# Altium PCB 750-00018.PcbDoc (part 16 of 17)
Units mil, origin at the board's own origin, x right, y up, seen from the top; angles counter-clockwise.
Board outline 7086.64 x 6299.21 mil, 8 copper layers (Top Layer, L2, L3, L4, L5, L6, L7, Bottom Layer), stack 60.6 mil thick; 1356 components, 1054 nets, 4851 pads, 4296 vias.
Unrouted connection lines stored in the file: 12.
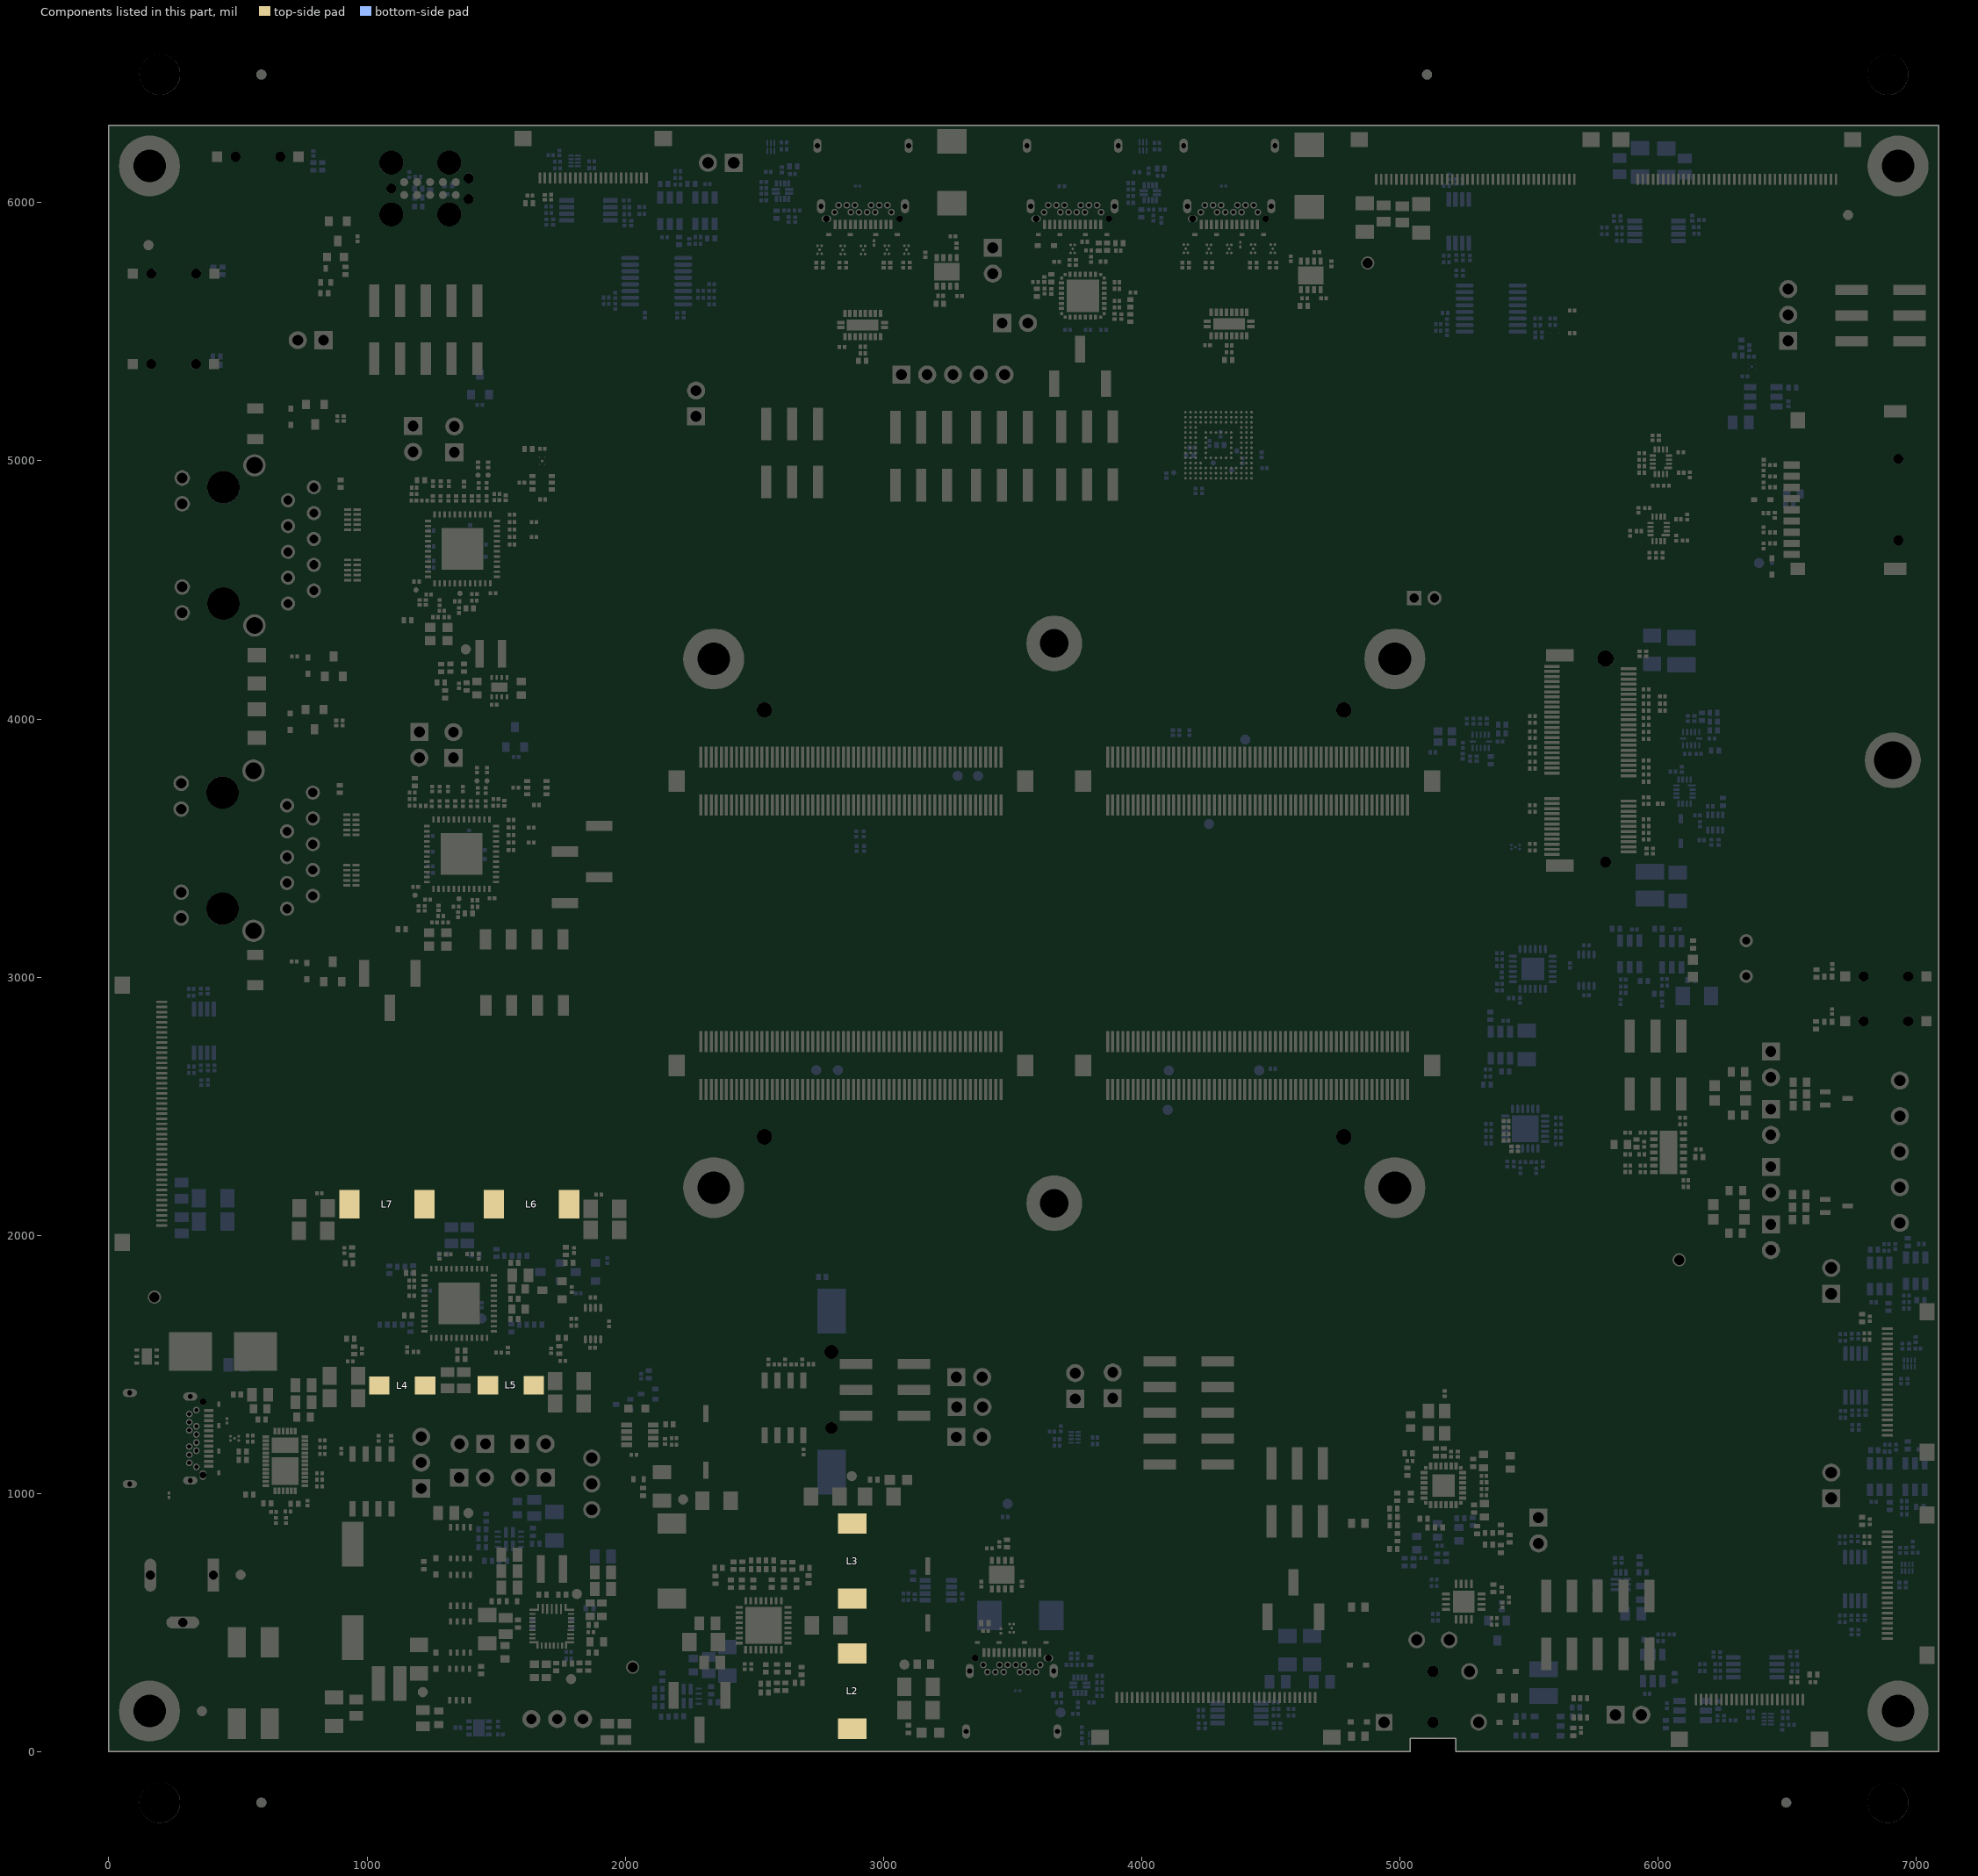
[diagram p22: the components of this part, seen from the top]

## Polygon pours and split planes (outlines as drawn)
GND on Top Layer "TOP-GND" (solid, remove dead copper, pour order 107): 0,0 5038.89,0 5038.89,51.18 5216.05,51.18 5216.05,0 7086.63,0 7086.63,6299.21 0,6299.21
AGND on Top Layer "TOP-AGND" (solid, remove dead copper, pour order 101): 4838.02,0 5038.89,0 5038.89,51.18 5216.05,51.18 5216.05,0 5417.44,0 5417.44,322.73 5507.23,412.52 5507.23,670.38 5615.15,778.3 5615.15,1028.18 5522.74,1120.59 5219.87,1120.59 5219.87,981.24 5116.08,981.24 5116.08,1182.17 5140.89,1206.98 5140.89,1279.36 5019.59,1279.36 4838.02,1097.79
VDD_5V on Top Layer "TOP-VDD_5V" (solid, remove dead copper, pour order 74): 2491.73,6081.68 2491.73,6033.64 2498.49,6026.89 2617.75,6026.89 2633.56,6011.07 2633.56,5843.45 2646.31,5830.7 2671.37,5830.7 2686.05,5845.37 2686.05,6162.48 2661.87,6186.66 2637.68,6186.66 2631.69,6180.67 2631.69,6101.64 2619.32,6089.26 2499.31,6089.26
VDD_5V on Top Layer "TOP-VDD_5V" (solid, remove dead copper, pour order 75): 3913.91,5977.95 4070.31,5821.56 4090.86,5821.56 4098.16,5828.85 4098.16,6168.01 4088.53,6177.64 4067.97,6177.64 4057.86,6167.54 4057.87,6039.46 4033.87,6015.46 3990.35,6015.46 3973.99,6031.82 3973.99,6078.98 3960.63,6092.34 3926.25,6092.34 3913.91,6080.01
GND_CHASE on Top Layer "TOP-GND_CHASE" (solid, remove dead copper, pour order 100): 7.28,5134.02 7.28,3028.3 650.91,3028.3 650.91,3982.23 518.38,3982.23 487.14,4013.47 487.14,4157.43 522.37,4192.66 654.86,4192.66 654.86,5134.02
CSI_HV on L3 "TOP-GND" (solid, remove dead copper, pour order 16): 4350.39,567.99 4350.39,461.36 4711.61,461.36 4711.61,1110.12 4930.51,1329.02 5319.83,1329.02 5445.32,1203.53 5542.87,1203.53 5666.82,1079.58 5666.82,668.48 5824.8,668.48 5824.8,1137.43 5475.78,1486.45 4742.98,1486.45 4464.85,1208.32 4464.85,682.45
GND on L3 "L3-GND" (solid, remove dead copper, pour order 121): 0,0 5038.89,0 5038.89,51.18 5216.05,51.18 5216.05,0 7086.63,0 7086.63,6299.21 0,6299.21
AGND on L3 "L3-AGND" (solid, remove dead copper, pour order 139): 4838.02,0 5038.89,0 5038.89,51.18 5216.05,51.18 5216.05,0 5417.44,0 5417.44,322.73 5507.23,412.52 5507.23,670.38 5615.15,778.3 5615.15,1028.18 5522.74,1120.59 5219.87,1120.59 5219.87,981.24 5116.08,981.24 5116.08,1182.17 5140.89,1206.98 5140.89,1279.36 5019.59,1279.36 4838.02,1097.79
NetC273_1 on L3 "L3-VL3-BUS_5V0_TYPEC_D_L03_P016" (solid, remove dead copper, pour order 55): 3590.02,5963.86 3590.02,5880.25 3649.07,5821.21 3893.51,5821.21 3922.04,5849.74 3922.04,5946.27 3871.93,5996.38 3622.54,5996.38
USB_A_VBUS on L3 "L3-VL3-BUS_5V0_TYPEC_D_L03_P016" (solid, remove dead copper, pour order 79): 3298.32,428.42 3298.32,344.82 3357.37,285.77 3601.81,285.77 3630.35,314.31 3630.35,410.83 3580.23,460.95 3330.85,460.95
VSYS_5V on L3 "NONET_L-01_P-001" (solid, remove dead copper, pour order 119): 2264.4,1342.26 2505.52,1342.26 2812.93,1649.67 2812.93,2040.82 3184.85,2412.74 3184.85,2817.81 3160.18,2842.47 3030.06,2842.47 2973.29,2785.7 2861.85,2785.7 2264.4,2188.26
NetD1_4 on L3 "L3-USB" (solid, remove dead copper, pour order 41): 229.58,1420.17 244.75,1405.01 327.86,1405.01 341.65,1391.21 341.65,1124.47 355.6,1110.52 411.66,1110.52 434.41,1133.27 434.41,1414.43 381.6,1467.24 238.13,1467.24 229.58,1458.69
VBUS_5V0_TYPEC_C on L3 "L3-VBL3-US_5V0_TYPEC_C_L03_P015" (solid, remove dead copper, pour order 69): 2694.82,5996.36 2694.82,5803.55 2755.05,5743.31 3193.06,5743.31 3268.64,5818.89 3268.64,5986.15 3209.37,6045.42 2743.88,6045.42
VBUS_5V0_TYPEC_D on L3 "L3-VL3-BUS_5V0_TYPEC_D_L03_P016" (solid, remove dead copper, pour order 76): 4131.45,6018.27 4131.45,5825.46 4191.69,5765.23 4588.66,5765.23 4651.68,5828.25 4651.68,6018.97 4603.32,6067.33 4180.51,6067.33
VPD_output on L3 "L3-VPD_OUTPUT_L03_P041" (solid, remove dead copper, pour order 84): 681.03,1448 681.03,1287.51 1182.8,785.74 1431.81,785.74 1441.37,795.31 1441.37,858.51 1432.06,867.81 1430.69,867.81 843.19,1455.31 688.34,1455.31
VDD_3V3 on L3 "L3-VDD_3V3_L03_P079" (solid, remove dead copper, pour order 98): 1639.03,1406.71 1639.03,1295.87 1919.62,1295.87 1919.62,2248.59 1593.42,2248.59 1593.42,1996.61 1716.02,1996.61 1716.02,1406.71
V_SYS on L3 "L3-V_SYS_L03_P084" (solid, remove dead copper, pour order 99): 1246.41,1996.61 1246.41,1828.55 1448.01,1828.55 1448.01,1640.87 1246.41,1640.87 1246.41,1072.71 1430.43,888.69 1700.48,888.69 2134.86,454.32 2696.88,454.32 2696.88,518.61 1919.62,1295.87 1639.03,1295.87 1639.03,1406.71 1716.02,1406.71 1716.02,1996.61
NetC76_2 on L3 "L3-NetC76_2" (solid, remove dead copper, pour order 104): 461.91,1077.23 476.9,1062.24 572.88,1062.24 625.02,1114.39 625.02,1230.62 666.71,1272.31 666.71,1449.63 656.54,1459.8 507.73,1459.8 461.91,1413.98
GND_CHASE on L3 "L3-GND_CHASE" (solid, remove dead copper, pour order 109): 7.28,5134.02 7.28,3028.3 650.91,3028.3 650.91,3982.23 518.38,3982.23 487.14,4013.47 487.14,4157.43 522.37,4192.66 654.86,4192.66 654.86,5134.02
GND on L4 "L4-GND" (solid, remove dead copper, pour order 110): 0,0 5038.89,0 5038.89,51.18 5216.05,51.18 5216.05,0 7086.63,0 7086.63,6299.21 0,6299.21
AGND on L4 "L4-AGND" (solid, remove dead copper, pour order 63): 4838.02,0 5038.89,0 5038.89,51.18 5216.05,51.18 5216.05,0 5417.44,0 5417.44,322.73 5507.23,412.52 5507.23,670.38 5615.15,778.3 5615.15,1028.18 5522.74,1120.59 5219.87,1120.59 5219.87,981.24 5116.08,981.24 5116.08,1182.17 5140.89,1206.98 5140.89,1279.36 5019.59,1279.36 4838.02,1097.79
GND_CHASE on L4 "L4-GND_CHASE" (solid, remove dead copper, pour order 56): 7.28,5134.02 7.28,3028.3 650.91,3028.3 650.91,3982.23 518.38,3982.23 487.14,4013.47 487.14,4157.43 522.37,4192.66 654.86,4192.66 654.86,5134.02
GND on L5 "L5-GND" (solid, remove dead copper, pour order 140): 0,0 5038.89,0 5038.89,51.18 5216.05,51.18 5216.05,0 7086.63,0 7086.63,6299.21 0,6299.21
VDD_3V3 on L5 "L5-VDD_3V3" (solid, remove dead copper, pour order 111): 1646.78,6190.36 1646.78,5912.86 2043.89,5912.86 2046.12,5910.62 2046.12,5880.07 2105.29,5880.07 2105.29,5912.76 4105.37,5912.76 4105.37,5288.79 4402.1,5288.79 4402.1,5378.22 4401.82,5377.95 4273.56,5377.95 4273.56,5558.89 4752.26,5558.89 4752.26,6075.94 4964.7,6075.94 4964.7,6008.56 6000.4,6008.56 6000.4,2899.21 5494.94,2899.21 5494.94,2626.14 6241,2626.14 6241,488.5 6241,265.56 6591.8,265.56 6591.8,6190.36
VDD_CSI_5V on L5 "L5-VDD_5V" (solid, remove dead copper, pour order 102): 6591.8,5901.54 6591.8,1111.3 7031.63,1111.3 7031.63,5901.54
AGND on L5 "L5-AGND" (solid, remove dead copper, pour order 126): 4838.02,0 5038.89,0 5038.89,51.18 5216.05,51.18 5216.05,0 5417.44,0 5417.44,322.73 5507.23,412.52 5507.23,670.38 5615.15,778.3 5615.15,1028.18 5522.74,1120.59 5219.87,1120.59 5219.87,981.24 5116.08,981.24 5116.08,1182.17 5140.89,1206.98 5140.89,1279.36 5019.59,1279.36 4838.02,1097.79
DP_HV on L5 "DP_12V" (solid, remove dead copper, pour order 115): 5100.16,1279.36 5100.16,5131.55 5100.16,6008.56 4964.7,6008.56 4964.7,6075.94 4752.26,6075.94 4752.26,4968.34 4604.43,4968.34 4604.43,242.26 4400.99,242.26 4400.99,329.59 521.61,329.59 521.61,2097.2 43.11,2097.2 43.11,41.03 4838.02,41.03 4838.02,1097.79 5019.59,1279.36
VDD_3V3 on L5 "L5-VDD_3V3_L05_P047" (solid, remove dead copper, pour order 57): 43.11,2255.29 43.11,2097.2 739.5,2097.2 739.5,1036.21 2881.88,1036.21 2881.88,559.09 4400.99,559.09 4400.99,242.26 4604.43,242.26 4604.43,826.17 3238.96,826.17 3238.96,1470.54 938.32,1470.54 938.32,2255.29
CSI_HV on L5 "TOP-CSI_HV" (solid, remove dead copper, pour order 48): 1679.92,1036.21 1679.92,769.52 2693.9,769.52 2693.9,329.59 4400.99,329.59 4400.99,559.09 2881.88,559.09 2881.88,1036.21
VDD_5V on L5 "L5-VDD_5V_L05_P048" (solid, remove dead copper, pour order 64): 4105.37,5913.22 938.32,5913.22 938.32,1470.54 1793.28,1470.54 3801.71,1470.54 3820.9,1489.72 3820.89,1680.54 3798.97,1702.47 1510.31,1702.47 1448.72,1640.87 1273,1640.87 1273,5588.81 4105.37,5588.81
VDD_3V3 on L5 "L5-VDD_3V3_L05_P080" (solid, remove dead copper, pour order 92): 1532.5,4095.95 1532.5,2193.15 1849.28,2193.15 1849.28,4095.95
GND_CHASE on L5 "L5-GND_CHASE" (solid, remove dead copper, pour order 123): 7.28,5134.02 7.28,3028.3 650.91,3028.3 650.91,3982.23 518.38,3982.23 487.14,4013.47 487.14,4157.43 522.37,4192.66 654.86,4192.66 654.86,5134.02
GND on L6 "L6-GND" (solid, remove dead copper, pour order 125): 0,0 5038.89,0 5038.89,51.18 5216.05,51.18 5216.05,0 7086.63,0 7086.63,6299.21 0,6299.21
VDD_CSI_5V on L6 "L6-VDD_5V" (solid, remove dead copper, pour order 112): 2283.12,6248.82 2283.12,5819.12 6790.92,5819.12 6790.92,6248.82
AGND on L6 "L6-AGND" (solid, remove dead copper, pour order 65): 4838.02,0 5038.89,0 5038.89,51.18 5216.05,51.18 5216.05,0 5417.44,0 5417.44,322.73 5507.23,412.52 5507.23,670.38 5615.15,778.3 5615.15,1028.18 5522.74,1120.59 5219.87,1120.59 5219.87,981.24 5116.08,981.24 5116.08,1182.17 5140.89,1206.98 5140.89,1279.36 5019.59,1279.36 4838.02,1097.79
GND_CHASE on L6 "L6-GND_CHASE" (solid, remove dead copper, pour order 58): 7.28,5134.02 7.28,3028.3 650.91,3028.3 650.91,3982.23 518.38,3982.23 487.14,4013.47 487.14,4157.43 522.37,4192.66 654.86,4192.66 654.86,5134.02
GND on Bottom Layer "BOT-GND" (solid, remove dead copper, pour order 138): 0,0 5038.89,0 5038.89,51.18 5216.05,51.18 5216.05,0 7086.63,0 7086.63,6299.21 0,6299.21
VDD_5V on Bottom Layer "VDD_5V_L08_P118" (solid, remove dead copper, pour order 118): 4042.9,5647.83 4042.9,5526.72 4113.03,5456.59 4570.05,5456.59 4675.83,5562.37 4675.83,5641.89 4664.34,5653.38 4615.9,5653.38 4545.56,5583.04 4161.34,5583.04 4108.77,5635.61 4086.43,5657.95 4053.03,5657.95
V_SYS on Bottom Layer "TOP-GND" (solid, remove dead copper, pour order 97): 2218.47,221.34 2218.47,251.84 2174.47,295.83 2132.21,295.83 2132.21,471.73 2147.87,487.39 2213.05,487.39 2234.22,466.22 2234.22,286.06 2234.22,221.34
LS_12V on Bottom Layer "Bottom Layer-LS_12V" (solid, remove dead copper, pour order 103): 1589.8,164.48 1912.19,164.48 2037.65,39.02 2221.11,39.02 2235.36,53.27 2235.36,208.39 2234.22,209.53 2218.47,209.53 2218.47,125.97 2205.97,113.47 2127.52,113.47 2123.16,117.82 2123.16,188.58 2052.41,188.58 1918.05,322.94 1664,322.94 1606.84,380.1 1606.84,714.48 1545.17,776.15 1545.17,817.49 1529.42,817.49 1529.42,754.07 1532.89,750.6 1532.89,728.26 1523.97,719.34 1444.72,719.34 1440.1,723.97 1440.1,804.57 1408.87,804.57 1372.13,767.83 1372.13,214.27 1460.55,125.85 1460.55,110.1 1514.41,110.1 1535.42,110.1
AGND on Bottom Layer "Bottom Layer-AGND" (solid, remove dead copper, pour order 135): 4838.02,0 5038.89,0 5038.89,51.18 5216.05,51.18 5216.05,0 5417.44,0 5417.44,322.73 5507.23,412.52 5507.23,670.38 5615.15,778.3 5615.15,1028.18 5522.74,1120.59 5219.87,1120.59 5219.87,981.24 5116.08,981.24 5116.08,1182.17 5140.89,1206.98 5140.89,1279.36 5019.59,1279.36 4838.02,1097.79
DP_HV on Bottom Layer "NONET_L-01_P-001" (solid, remove dead copper, pour order 114): 4899.35,6169.32 4899.35,6046.86 4916.96,6029.25 4945.77,6029.25 5028.77,6112.25 5694.64,6112.25 5776.66,6030.23 5958.58,6030.23 5972.52,6044.18 5972.52,6132.16 5810.3,6132.16 5719.41,6223.05 4953.07,6223.05
V_SYS2 on Bottom Layer "NONET_L-01_P-001" (solid, remove dead copper, pour order 116): 1772.21,797.48 1820.91,748.78 1820.91,613.56 1830.24,604.23 1901.3,604.23 1901.3,783 1971.09,852.78 1971.09,1031.64 1927.5,1075.23 1804.59,1075.23 1772.21,1042.85
GND_CHASE on Bottom Layer "BOT-GND_CHASE" (solid, remove dead copper, pour order 127): 7.28,5134.02 7.28,3028.3 650.91,3028.3 650.91,3982.23 518.38,3982.23 487.14,4013.47 487.14,4157.43 522.37,4192.66 654.86,4192.66 654.86,5134.02
GND on L2 "L2-GND" (solid, remove dead copper, pour order 108): 0,0 5038.89,0 5038.89,51.18 5216.05,51.18 5216.05,0 7086.63,0 7086.63,6299.21 0,6299.21
GND_CHASE on L2 "L2-GND_CHASE" (solid, remove dead copper, pour order 54): 7.28,5134.02 7.28,3028.3 650.91,3028.3 650.91,3982.23 518.38,3982.23 487.14,4013.47 487.14,4157.43 522.37,4192.66 654.86,4192.66 654.86,5134.02
AGND on L2 "L2-AGND" (solid, remove dead copper, pour order 61): 4838.02,0 5038.89,0 5038.89,51.18 5216.05,51.18 5216.05,0 5417.44,0 5417.44,322.73 5507.23,412.52 5507.23,670.38 5615.15,778.3 5615.15,1028.18 5522.74,1120.59 5219.87,1120.59 5219.87,981.24 5116.08,981.24 5116.08,1182.17 5140.89,1206.98 5140.89,1279.36 5019.59,1279.36 4838.02,1097.79
GND on L7 "L7-GND" (solid, remove dead copper, pour order 113): 0,0 5038.89,0 5038.89,51.18 5216.05,51.18 5216.05,0 7086.63,0 7086.63,6299.21 0,6299.21
AGND on L7 "L7-AGND" (solid, remove dead copper, pour order 66): 4838.02,0 5038.89,0 5038.89,51.18 5216.05,51.18 5216.05,0 5417.44,0 5417.44,322.73 5507.23,412.52 5507.23,670.38 5615.15,778.3 5615.15,1028.18 5522.74,1120.59 5219.87,1120.59 5219.87,981.24 5116.08,981.24 5116.08,1182.17 5140.89,1206.98 5140.89,1279.36 5019.59,1279.36 4838.02,1097.79
GND_CHASE on L7 "L7-GND_CHASE" (solid, remove dead copper, pour order 59): 7.28,5134.02 7.28,3028.3 650.91,3028.3 650.91,3982.23 518.38,3982.23 487.14,4013.47 487.14,4157.43 522.37,4192.66 654.86,4192.66 654.86,5134.02

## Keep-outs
Top Layer:
  region: 654.76,3843.27 1000.99,3843.27 1256.56,3587.91 1256.56,3361.7 1002.08,3143.27 654.76,3143.27
  region: 658.71,5025.59 1004.93,5025.59 1260.5,4770.22 1260.5,4544.02 1006.02,4325.59 658.71,4325.59
L3:
  lines w8: 1593.42,1996.61 1593.42,2248.59 1919.62,2248.59 1919.62,1295.87 ; 1919.62,1295.87 2696.88,518.61 2696.88,454.32 2134.86,454.32 1700.48,888.69 1627.4,888.69 1430.43,888.69 1246.41,1072.71 1246.41,1640.87 1448.01,1640.87 1448.01,1828.55 1246.41,1828.55 1246.41,1996.61 1716.02,1996.61 1716.02,1406.71 1639.03,1406.71 1639.03,1295.87 1919.62,1295.87 ; 2264.4,1342.26 2264.4,1470.54 2264.4,2188.26 2861.85,2785.7 2973.29,2785.7 3030.06,2842.47 3160.18,2842.47 3184.85,2817.81 3184.85,2412.74 2812.93,2040.82 2812.93,1649.67 2505.52,1342.26 2264.4,1342.26 ; 2694.82,5803.55 2755.05,5743.31 3193.06,5743.31 3268.64,5818.89 3268.64,5986.15 3209.37,6045.42 2743.88,6045.42 2694.82,5996.36 2694.82,5803.55 ; 3298.32,343.41 3355.96,285.77 3601.81,285.77 3630.35,314.31 3630.35,410.83 3580.23,460.95 3330.85,460.95 3298.32,428.42 3298.32,343.41 ; 3590.02,5878.84 3590.02,5963.86 3622.54,5996.38 3871.93,5996.38 3922.04,5946.27 3922.04,5849.74 3893.51,5821.21 3647.66,5821.21 3590.02,5878.84 ; 4131.45,5825.46 4131.45,6018.27 4180.51,6067.33 4603.32,6067.33 4651.68,6018.97 4651.68,5828.25 4588.66,5765.23 4191.69,5765.23 4131.45,5825.46
  lines w10: 4350.39,461.36 4350.39,567.99 4464.85,682.45 4464.85,1208.32 4742.98,1486.45 5475.78,1486.45 5617.58,1344.66 5824.8,1137.43 5824.8,700.24 5824.8,668.48 5666.82,668.48 5666.82,1079.58 5542.87,1203.53 5445.32,1203.53 5319.83,1329.02 4930.51,1329.02 4711.61,1110.12 4711.61,461.36 4350.39,461.36
L5:
  lines w8: 938.32,2255.29 43.11,2255.29 43.11,2097.2 ; 1646.78,5912.86 938.32,5912.86 938.32,1470.54 1798.97,1470.54 ; 4604.43,826.17 3238.96,826.17 3238.96,1470.54 1798.97,1470.54 ; 4838.02,0 4838.02,1097.79 5019.59,1279.36 5100.16,1279.36 5140.89,1279.36 5140.89,1206.98 5116.08,1182.17 5116.08,981.24 5219.87,981.24 5219.87,1120.59 5522.74,1120.59 5615.15,1028.18 5615.15,778.3 5507.23,670.38 5507.23,412.52 5417.44,322.73 5417.44,0 ; 4838.02,41.03 151.95,41.03 43.11,149.87 43.11,2097.2 ; 5100.16,1280.21 5100.16,1770.09 ; 5100.16,5418.01 5100.16,1770.09 ; 6591.8,1111.3 7031.63,1111.3 7031.62,5901.54 6591.8,5901.54 ; 43.11,2097.2 521.61,2097.2 ; 521.61,2097.2 739.5,2097.2 739.5,1036.21 2881.88,1036.21 2881.88,559.09 4400.99,559.09 4400.99,329.59 ; 521.61,2097.2 521.61,329.59 4400.99,329.59 ; 1798.97,1470.54 3706.97,1470.54 3801.71,1470.54 3822.13,1490.95 3822.13,1679.31 3798.97,1702.47 1510.31,1702.47 1448.72,1640.87 1273,1640.87 1272.99,5588.81 4105.37,5588.81 ; 4105.37,5588.81 4105.37,5912.76 2105.29,5912.76 2105.29,5880.07 2046.12,5880.07 2046.12,5912.76 1646.78,5912.76 1646.78,6190.36 6079.78,6190.36 6591.8,6190.36 6591.8,265.56 6241,265.56 6241,2626.14 5494.94,2626.14 5494.94,2899.21 6000.4,2899.21 6000.4,6008.56 ; 4105.37,5588.81 4105.37,5288.79 4402.1,5288.79 4402.1,5377.95 4273.56,5377.95 4273.56,5558.89 4752.26,5558.89 ; 4400.99,329.59 4400.99,242.26 4604.43,242.26 4604.43,4787.4 4604.43,4968.34 4752.26,4968.34 4752.26,5558.89 ; 4752.26,5558.89 4752.26,6075.94 4964.7,6075.94 4964.7,6008.56 5100.16,6008.56 ; 5100.16,1770.09 5100.16,6008.56 ; 5100.16,6008.56 6000.4,6008.56 ; 6000.4,6008.56 6000.4,6008.56 ; 1532.5,2193.15 1532.5,4095.95 1849.28,4095.95 1849.28,2193.15 1593.42,2193.15 1532.5,2193.15
  lines w10: 1680.41,1036.21 1679.92,1036.21 1679.92,769.52 2693.9,769.52 2693.9,329.59 2742.82,329.59
L6:
  lines w8: 2283.12,5819.12 6790.92,5819.12 6790.92,6248.82 2283.12,6248.82 2283.12,6037.26 2283.12,5819.12
Bottom Layer:
  lines w8: 4042.9,5636.09 4042.9,5647.44 4053.42,5657.95 4086.43,5657.95 4161.34,5583.04 4545.56,5583.04 4615.9,5653.38 4664.34,5653.38 4675.83,5641.89 4675.83,5562.37 4570.05,5456.59 4113.03,5456.59 4042.9,5526.72 4042.9,5636.09 ; 4042.9,5636.09 4042.94,5636.09 ; 4899.35,6046.86 4899.35,6169.32 4953.07,6223.05 5719.41,6223.05 5810.3,6132.16 5960.57,6132.16 5972.52,6120.2 5972.52,6044.18 5958.58,6030.23 5776.66,6030.23 5694.64,6112.25 5028.77,6112.25 4945.77,6029.25 4916.96,6029.25 4899.35,6046.86
Keep-Out Layer:
  lines w5: 0,6299.21 7086.63,6299.21 7086.63,0 5216.45,0 5216.45,51.18 5039.28,51.18 5039.28,0 0,0 0,6299.21
  lines w8: 0,3028.3 650.91,3028.3 650.91,3982.23 518.38,3982.23 486.5,4014.1 ; 3.94,5134.02 654.86,5134.02 654.86,4192.66 522.37,4192.66 487.14,4157.43 487.14,4013.47 ; 4838.02,0 4838.02,1097.79 5019.59,1279.36 5140.89,1279.36 5140.89,1206.98 5116.32,1182.4 5116.32,980.54 5220.95,980.54 5220.95,1120.59 5522.74,1120.59 5615.15,1028.18 5615.15,778.3 5507.23,670.38 5507.23,412.52 5417.44,322.73 5417.44,0

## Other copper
Top Layer:
  pour cut-out: 6735.52,5981.81 ccw(c6735.52,5952.12) 6705.84,5952.12 ccw(c6735.52,5952.12) 6735.52,5922.44 ccw(c6735.52,5952.12) 6765.21,5952.12 ccw(c6735.52,5952.12)
  pour cut-out: 153.48,5865.01 ccw(c153.48,5835.32) 123.79,5835.32 ccw(c153.48,5835.32) 153.48,5805.64 ccw(c153.48,5835.32) 183.16,5835.32 ccw(c153.48,5835.32)
  pour cut-out: 360.48,187.17 ccw(c360.48,157.48) 330.79,157.48 ccw(c360.48,157.48) 360.48,127.8 ccw(c360.48,157.48) 390.16,157.48 ccw(c360.48,157.48)
  region net VDD_3V3_D: 6555.07,202.02 6564.91,202.02 6564.91,244.56 6582.22,261.87 6595.81,261.87 6595.81,311.28 6578.03,311.28 6555.07,288.32
  region net PER_12V: 1332.29,142.94 1347.16,128.06 1392.51,128.06 1442.6,178.15 1572.04,178.15 1581.21,187.32 1581.21,316.76 1664.39,399.94 1664.39,427.5 1628.96,427.5 1628.96,403.08 1508.23,282.35 1258.58,282.35 1209.52,331.41 1101.13,331.41 1101.13,187.61 1145.81,142.94
  region net V_SYS: 1322.43,1597.84 1322.43,1527.34 1284.77,1489.69 1284.77,1452.29 1401.12,1452.29 1401.6,1451.8 1401.6,1489.2 1379.49,1489.2 1358.26,1510.44 1358.26,1584.51 1351.56,1591.21 1351.56,1597.84
  region net V_SYS: 1342.11,1874.68 1342.11,1885.13 1338.67,1888.57 1338.67,1944.21 1342.84,1948.39 1370.97,1948.39 1374.53,1944.83 1374.53,1888.23 1371.25,1884.95 1371.25,1874.68
  region net V_SYS: 2434.56,504.91 2403.7,504.91 2384.78,523.83 2331.16,523.83 2331.16,389.57 2386.28,389.57 2386.28,436.65 2424.21,474.58 2434.56,474.58
  region net V_SYS: 2633.76,504.91 2633.76,474.58 2650.35,474.58 2671.19,453.74 2750.45,453.74 2750.45,524.61 2671.19,524.61 2651.49,504.91
  region net V_SYS: 1478.73,1801.06 1525.88,1801.06 1544.04,1819.21 1581.44,1819.21 1581.44,1872.36 1537.42,1872.36 1511.79,1846.73 1511.79,1819.95 1502.35,1810.51 1478.73,1810.51
  region net DP_HV: 4624.03,302 4624.03,234.67 4627.37,231.33 4627.37,219.3 4656.9,219.3 4656.9,302.75 4652.73,306.91 4628.94,306.91
  region net DP_HV: 183.19,2082.38 183.19,2052.85 249.93,2052.85 252.04,2054.96 252.04,2079.43 249.1,2082.38
  region net DP_HV: 4922.52,6082.35 4922.52,6067.61 4879.7,6024.78 4828.39,6024.78 4828.39,5969.67 4951.13,5969.67 4963.61,5982.14 4963.61,6056.05 4952.05,6067.61 4952.05,6082.35
  region net DP_HV: 5935.93,6080.25 5935.93,6068.94 5924.26,6057.27 5924.26,6048.24 5931.41,6041.08 5957.74,6041.08 5965.46,6048.8 5965.46,6080.25
  region net SDIO_B_IOPWR: 3862.21,3851.92 3862.21,3893.26 3837.73,3917.74 3837.73,3932.41 3840.38,3935.07 3849.06,3935.07 3874.02,3910.11 3874.02,3851.92
  pour cut-out: 5311.78,2672.62 5325.6,2672.62 5325.6,2678.54 5311.8,2678.54 5311.8,2672.66
  region net VDD_3V3_A: 1673.92,6095.14 1673.92,5995.39 1664.42,5985.89 1633.73,5985.89 1633.73,6035.43 1646.91,6035.43 1664.07,6052.6 1664.07,6095.14
  region net VDD_3V3_B: 6887.83,1634.03 6788.07,1634.03 6778.57,1643.53 6778.57,1674.22 6828.12,1674.22 6828.12,1661.05 6845.29,1643.88 6887.83,1643.88
  region net VDD_3V3_C: 6887.83,847.06 6788.07,847.06 6778.57,856.56 6778.57,888.07 6827.98,888.07 6827.98,874.21 6845.29,856.9 6887.83,856.9
  region net VDD_3V3: 5994.99,6080.48 5994.99,6047.96 6003.62,6039.32 6057.12,6039.32 6059.01,6041.21 6059.01,6054.13 6044.2,6068.94 6044.2,6080.48
  region net VDD_3V3: 4981.58,6081.6 4981.58,5966.9 4982.02,5966.45 5117.5,5966.45 5117.75,5966.7 5117.75,6021.82 5065.1,6021.82 5030.79,6056.13 5030.79,6081.6
  region net VDD_3V3: 4341.09,5303.38 4346.18,5298.28 4358,5298.28 4362.37,5302.66 4362.37,5457.15 4354.87,5464.66 4354.87,5498.49 4341.09,5498.49 4341.09,5382.69
  region net VDD_3V3: 2922.61,5324.35 2925.68,5321.29 2940.37,5321.29 2943.9,5324.81 2943.9,5453.03 2936.39,5460.54 2936.39,5494.37 2922.61,5494.37 2922.61,5378.58
  region net VDD_3V3: 1516.83,4081.87 1516.83,4059.28 1521.35,4054.76 1610.92,4054.76 1615.86,4059.7 1615.86,4107.12 1579.86,4107.12 1554.61,4081.87
  region net VDD_3V3: 4548.63,219.3 4548.63,271.84 4582.25,305.46 4594.27,305.46 4597.84,301.89 4597.84,219.3
  region net VDD_3V3: 2087.08,1256.88 2165.17,1256.88 2165.17,1280.57 2148.08,1297.65 2092.14,1297.65 2087.08,1292.6 2087.08,1274.6
  region net VDD_3V3: 183.19,2161.12 248.22,2161.12 251.57,2157.77 251.57,2114.55 248.92,2111.9 183.19,2111.9
  region net VDD_3V3: 1755.27,1550.02 1755.27,1311.89 1746.96,1303.58 1634.87,1303.58 1606.79,1331.66 1606.79,1514.95 1641.86,1550.02 1743.43,1550.02
  region net VSYS_5V: 3015.75,2781.08 3165.36,2781.08 3165.36,2811.88 3153.98,2823.26 3026.81,2823.26 3015.75,2812.2
  region net VSYS_5V: 2332.22,1276.15 2332.22,1343.08 2332.19,1343.1 2322.24,1343.1 2322.24,1276.18 2302.56,1276.18 2302.56,1343.1 2302.53,1343.08 2292.52,1343.08 2292.52,1276.15 2243.31,1276.15 2243.31,1367.74 2281.82,1406.24 2362.76,1406.24 2381.29,1387.72 2381.29,1276.15
  region net VSYS_3V3: 3191.47,685.3 3240.64,685.3 3240.64,772.53 3240.64,829.87 3182.3,888.21 3115.44,888.21 3102.56,875.33 3102.56,685.3 3151.77,685.3 3151.77,752.23 3161.78,752.23 3161.81,752.26 3161.81,685.33 3181.5,685.33 3181.5,752.26 3191.44,752.26 3191.47,752.23
  region net VSYS_3V3: 2858.27,2544.9 2858.27,2500.33 2865.61,2492.99 2883.13,2492.99 2889.77,2499.63 2889.77,2544.9
  region net VSYS_3V3: 2849.56,1911.87 2849.56,1883.76 2860.04,1873.29 2887.22,1873.29 2899.38,1885.45 2899.38,1911.87
  region net NetL13_1: 1516.83,4173.61 1506.27,4184.17 1506.27,4301.2 1537.76,4301.2 1537.76,4181.74 1526.67,4170.65 1526.67,4150.97 1516.83,4150.97
  region net VBUS_5V0_TYPEC_A: 3368.83,486.06 3386.61,486.06 3386.61,507.29 3478.5,599.18 3478.5,644.29 3478.87,644.67 3437.53,644.67 3437.53,600.53 3368.83,531.83
  region net NetC273_1: 3854.63,5857.7 3854.63,5835.2 3885.85,5835.2 3889.17,5831.88 3906.95,5831.88 3906.95,5875.27 3902.33,5879.89 3890.92,5879.89 3875.91,5864.88 3861.82,5864.88
  region net NetD1_4: 368.84,1268.5 363,1274.34 363,1289.67 353.69,1298.98 338.59,1298.98 331.66,1292.05 331.66,1254.89 336.31,1250.24 362.39,1250.24 368.84,1256.69 404.27,1256.69 404.27,1268.5
  region net NetD1_4: 368.84,1158.27 363,1152.43 363,1137.1 353.69,1127.79 338.59,1127.79 331.66,1134.72 331.66,1171.88 335.85,1176.07 362.85,1176.07 368.84,1170.08 404.27,1170.08 404.27,1158.27
  region net NetD1_4: 175.62,1500.06 221.43,1454.24 378.44,1454.24 400.12,1475.93 400.12,1625.93 233.19,1625.93 175.62,1568.35
  region net RING2: 5165.2,557.3 5137.79,557.3 5118.89,538.39 5118.89,522.88 5146.14,522.88 5146.14,528.8 5165.2,547.86
  region net SLEEVE: 5165.88,595.75 5128.04,605.89 5128.12,577.02 5165.88,586.56
  region net GND_DC: 71.52,745.3 71.52,418.74 199.3,290.95 509.07,290.95 541.22,323.1 541.22,478.97 522.07,498.11 415.86,498.11 359.46,441.71 214.91,441.71 184.53,472.09 184.53,553.7 212.21,581.37 212.2,744.51 184.32,772.4 98.61,772.4
  region net DCJACK12V: 344.38,743.67 344.38,583.04 366.48,560.95 509.17,560.95 572.85,497.26 572.85,321.84 604.72,289.98 686.17,289.98 720.88,324.68 720.88,649.81 598.29,772.4 373.11,772.4
  region net ENET_1V0: 1297.64,4167.81 1289.98,4160.14 1289.98,4101.78 1313.67,4101.78 1343.53,4131.64 1443.62,4131.64 1451.15,4139.17 1451.15,4301.2 1419.65,4301.2 1419.65,4194.02 1393.44,4167.81
  region net MICP: 5251.33,642.57 5251.33,674.06 5249.41,682.06 5264.34,682.06 5262.36,674.06 5262.36,642.57
  region net NetC297_1: 6516.95,4867.3 6430.98,4867.3 6422.67,4859 6422.67,4839.32 6436.78,4825.21 6470.92,4825.21 6485.45,4839.74 6516.95,4839.74
  region net VDD_3V3_M2: 5895.59,4168.43 5945.57,4168.43 5961.65,4184.51 5961.65,4249.74 5920.15,4249.74 5920.02,4249.87 5895.59,4225.44
  region net VDD_3V3_M2: 5897.68,3510.95 5897.68,3468 5919.24,3446.44 6039.29,3446.44 6045.09,3452.24 6045.09,3477.86 6036.96,3485.98 5936.51,3485.98 5911.55,3510.95
  region net AUD_3V3: 5315.9,616.38 5331.65,616.38 5339.65,618.31 5339.65,603.37 5331.65,605.36 5315.9,605.36
  region net VBUS_5V0_TYPEC_D: 4633.9,5776.86 4675.24,5776.86 4675.24,5893.61 4706.29,5924.66 4706.29,6030.77 4592.12,6030.77 4592.12,5828.82 4633.9,5787.03
  region net VBUS_5V0_TYPEC_C: 3224.08,5773.42 3265.42,5773.42 3265.42,5881.97 3322.06,5938.61 3322.06,6044.72 3207.89,6044.72 3207.89,5817.18 3224.08,5800.98
  region net USB_A_VBUS: 3398.36,509.74 3398.48,509.62 3398.48,460.39 3386.38,448.28 3386.38,438.89 3386.5,438.89 3394.05,431.34 3426.92,431.34 3434.19,438.62 3434.19,491.69 3416.14,509.74
  region net NetC110_1: 575.36,51.72 593.31,33.77 709.8,33.77 855.64,179.6 1051.69,179.6 1069.64,197.55 1069.64,535.85 1030.56,574.93 873.98,574.93 838.21,539.16 838.21,371.3 703.38,236.47 606.72,236.47 575.36,205.11
  region net V_SYS2: 1761.48,619.8 1761.48,596.11 1898.03,596.11 1901.09,599.17 1901.09,720.97 1841.58,720.97 1834.08,713.47 1834.08,646.98 1806.9,619.8
  region net PMID: 1613.58,596.27 1600.87,608.98 1563.47,608.98 1563.47,788.56 1564.71,789.8 1600.87,789.8 1600.87,662.13 1643.04,619.96 1665.29,619.96 1665.29,596.27
  region net U28_SW2: 1743.36,761.11 1788.55,761.11 1802.16,747.51 1802.16,659.72 1793.49,651.05 1747.12,651.05 1743.36,654.81
  region net U28_SW2: 1737.23,573.17 1737.23,533.8 1742.96,528.07 1766.09,528.07 1772.12,522.04 1772.12,491.55 1766.33,485.76 1736.24,485.76 1729.35,492.65 1729.35,573.17
  region net U28_SW1: 1693.92,573.17 1693.92,533.8 1689.15,529.03 1666.02,529.03 1659.03,522.04 1659.03,491.55 1664.82,485.76 1694.91,485.76 1701.79,492.65 1701.79,573.17
  region net U28_SW1: 1688.24,761.11 1643.05,761.11 1629.45,747.51 1629.45,659.72 1638.24,650.93 1684.36,650.93 1688.24,654.81
  region net NetC92_1: 1380.83,760.6 1317.84,760.6 1317.84,723.42 1343.73,697.53 1343.73,673.91 1406.72,673.91 1406.72,697.53 1380.83,723.42
  region net BAT_SENSE-: 1793.81,105.91 1809.17,90.54 2023.6,90.54 2073.37,140.31 2073.37,444.95 1980.05,538.26 1778.57,538.26 1778.57,514.12 1840.12,514.12 1843.97,510.26 1927.27,510.26 1986,451.54 1986,444.04 1901.63,444.04 1901.63,408.04 1981.8,408.04 1989.25,400.59 1989.25,188.9 1971.83,171.48 1815.9,171.48 1793.81,149.39
  region net NetC89_1: 1640.77,537.74 1519.68,537.74 1500.26,557.17 1430.36,557.17 1410.66,576.86 1410.66,646.76 1314.2,646.76 1313.87,646.42 1313.87,422.54 1410.32,422.54 1410.32,492.43 1419.94,502.05 1596.28,502.05 1608.35,514.12 1640.77,514.12
  region net NetC88_1: 1380.87,395.38 1317.88,395.38 1317.88,358.2 1339.03,337.05 1339.03,308.69 1402.02,308.69 1402.02,337.05 1380.87,358.2
  region net VPD_output: 1313.06,784.87 1409.52,784.87 1409.52,950.44 1406.96,953 1316.91,953 1313.06,949.15
  region net VPD_output: 686.95,1303.75 686.95,1228.23 728.13,1228.23 728.13,1253.82 740.8,1266.48 740.8,1296.05 741.94,1296.05 741.94,1444.76 734.12,1452.58 689.29,1452.58 683.22,1446.51 683.22,1307.48
  region net NetC76_2: 569.59,1129.71 549.74,1109.86 498.19,1109.86 491.19,1102.86 491.19,1073.33 495.97,1068.55 554.48,1068.55 592.09,1106.16 607.06,1106.16 607.06,1129.71
  region net NetC76_2: 677.72,1253.88 673.04,1258.56 673.04,1603.87 651.15,1625.76 483.98,1625.76 483.98,1448.91 515.25,1417.65 590.91,1417.65 598.49,1410.07 598.49,1267.32 637.57,1228.23 677.72,1228.23
  region net NetC75_2: 619.86,1034.22 594.27,1034.22 567.95,1007.9 550.17,1007.9 550.17,984.21 578.6,984.21 619.86,1025.47
  region net VDD_2V5: 818.16,2170.99 818.16,1985.61 859.15,1944.61 954.42,1944.61 954.49,1944.54 970.46,1960.51 970.46,2176.22 823.38,2176.22
  region net SW4: 1331.53,1858.93 1322.43,1858.93 1322.43,1882.55 1318.57,1886.41 1318.57,1940.16 1182.92,2075.81 1182.92,2176.23 1305.99,2176.23 1331.53,2150.68
  region net NetC57_1: 1478.73,1731.77 1572.53,1731.77 1572.53,1699.15 1525.52,1699.15 1502.35,1722.32 1478.73,1722.32
  region net VDDD: 1478.73,1771.14 1506.93,1771.14 1546.14,1810.35 1574.14,1810.35 1574.14,1774.35 1546.14,1774.35 1533.48,1761.69 1478.73,1761.69
  region net VDDD: 1169.54,1808.28 1145.55,1808.28 1135.47,1798.2 1135.47,1767.84 1145.05,1758.26 1169.69,1758.26 1169.69,1808.13
  region net VDD_1V8: 6083.7,2328.84 6083.7,2313.09 6111.26,2313.09
  region net VDD_1V8: 5243.49,1087.64 5243.49,1074.26 5294.37,1074.26 5305.69,1085.57 5338.6,1085.57 5338.6,1110.48 5279.72,1110.48 5256.88,1087.64
  region net VDD_1V8: 1895.34,2171 1895.34,1985.61 1854.34,1944.61 1759.07,1944.61 1759,1944.55 1743.03,1960.51 1743.03,2176.23 1890.11,2176.23
  region net NetC49_2: 1381.48,1858.93 1390.93,1858.93 1390.93,1882.55 1394.79,1886.41 1394.79,1940.16 1530.43,2075.81 1530.43,2176.23 1407.37,2176.23 1381.48,2150.34 1381.48,1882.55
  region net NetC42_2: 1401.17,1538.11 1428.81,1510.47 1428.81,1383.36 1507.09,1383.36 1507.09,1534.11 1507.09,1554.38 1486.82,1554.38 1449.99,1591.21 1449.99,1597.84 1401.17,1597.84
  region net VDD_5V: 4633.9,5676.8 4633.97,5676.73 4633.97,5576.32 4638.37,5571.92 4669.82,5571.92 4675.24,5577.35 4675.24,5676.8 4633.9,5676.8
  region net VDD_5V: 3224.14,5690.75 3224.14,5590.27 3228.54,5585.87 3259.99,5585.87 3265.42,5591.3 3265.42,5690.75
  region net VDD_5V: 3490.85,800.71 3490.61,800.46 3441.18,800.46 3437.53,796.82 3437.53,744.77 3468.74,744.77 3490.85,766.88 3490.85,800.71 3490.61,800.46 3441.18,800.46
  region net VDD_5V: 937.67,1549.16 937.67,1311.03 945.97,1302.72 1059.8,1302.72 1086.18,1329.11 1086.18,1525.18 1062.21,1549.16 949.51,1549.16
  region net NetC32_2: 1185.39,1383.36 1264.13,1383.36 1264.13,1490.05 1312.19,1538.11 1312.19,1597.84 1263.37,1597.84 1263.37,1591.21 1228.92,1556.76 1192.27,1556.76 1192.27,1537.18 1185.39,1530.3 1185.39,1513.23
  region net VDD_OSM_1V8: 3907.1,5699.3 3907.13,5699.27 3907.13,5611.34 3935.18,5611.34 3939.76,5615.92 3963.19,5615.92 3963.19,5633.44 3963.19,5676.84 3940.73,5699.3
  region net VDD_OSM_1V8: 2801.89,867.16 2824,845.06 2934.23,845.06 2957.38,868.21 2957.38,1065.4 2934.23,1088.54 2824.24,1088.54 2801.61,1065.91 2801.89,1065.63 2801.89,1014.68
  region net NetC20_2: 2615.98,533.68 2658.69,533.68 2928.85,533.68 2940.54,545.37 2940.54,651.56 2930.37,661.72 2714.77,661.72 2698.09,645.05 2698.09,596.45 2645.96,544.31 2615.98,544.31
  region net VDD_OSM_0_3V3: 2731.48,47.01 2741.73,36.75 3023.99,36.75 3081.02,93.78 3108.55,93.78 3108.55,284.96 3144.37,320.77 3144.37,369.78 3240.43,465.84 3240.43,532.77 3191.22,532.77 3191.22,465.84 3181.5,465.84 3181.5,532.77 3161.81,532.77 3161.81,465.84 3152.17,465.84 3152.09,465.92 3152.09,532.84 3102.88,532.84 3102.88,465.92 3012.21,375.25 3012.21,219.16 2978.53,185.47 2749.18,185.47 2731.48,167.77
  region net NetC9_2: 2615.98,445.81 2658.69,445.81 2928.85,445.81 2940.54,434.13 2940.54,327.94 2931.71,319.12 2671.04,319.12 2667.66,322.5 2667.66,413.68 2646.15,435.18 2615.98,435.18
  region net VDD_OSM_S_M_5V: 2057.12,1000.09 2057.12,913.39 2125.45,845.06 2235.69,845.06 2327.07,936.44 2327.07,1008.96 2335.16,1017.05 2373.5,1017.05 2381.3,1024.85 2381.3,1123.56 2332.09,1123.56 2332.09,1056.63 2322.29,1056.63 2322.24,1056.69 2322.24,1123.62 2302.56,1123.62 2302.56,1056.69 2292.71,1056.69 2292.71,1123.62 2243.5,1123.62 2243.5,1064.56 2179.03,1000.09
  region net NetC4_2: 2454.54,533.68 2411.84,533.68 2141.67,533.68 2125.45,549.9 2125.45,647.02 2138.81,660.38 2353.69,660.38 2363.29,650.78 2363.29,605.79 2424.76,544.31 2454.54,544.31
  pour cut-out: 5440.84,818.04 5454.02,818.04 5454.02,832.77 5440.84,832.77
  pour cut-out: 5311.57,2610.89 5325.39,2610.89 5325.39,2616.81 5311.59,2616.81 5311.59,2610.93
  pour cut-out: 3246.95,4810.94 3256.72,4801.17 3260.91,4805.35 3251.15,4815.11 3247,4810.95
  pour cut-out: 2700.79,3893.26 2889.77,3893.26 2889.77,4358.48 2198.12,5050.13 2135.42,5050.13 2080.45,5105.1 1972.42,5105.1 1895.5,5182.01 1812.73,5182.01 1812.03,5182.72 1812.03,5174.95 2700.79,4286.18
  pour cut-out: 4313.8,3893.23 4327.61,3893.23 4327.61,3899.14 4313.82,3899.14 4313.82,3893.26
  pour cut-out: 4179.22,4086.7 4193.04,4086.7 4193.04,4092.62 4179.24,4092.62 4179.24,4086.74
  pour cut-out: 1481.34,4614.2 1481.34,4576.37 1649.54,4576.37 1657.99,4567.92 1657.99,4304.19 2018.93,3943.25 2351.17,3943.25 2394.16,3900.26 2544.54,3900.26 2544.54,3965.02 2407.11,4102.44 2199.89,4102.44 2017.86,4284.48 2017.86,4590.27 1896.26,4711.87 1578.96,4711.87 1480.39,4613.3
  pour cut-out: 567,2416.08 567,2402.27 572.92,2402.27 572.92,2416.06 567.04,2416.06
  pour cut-out: 427.66,2636.25 427.66,2622.43 433.58,2622.43 433.58,2636.23 427.69,2636.23
  pour cut-out: 1513.64,1522.02 1513.64,1317.3 1600.26,1317.3 1600.26,1522.02
  pour cut-out: 1092.68,1521.16 1092.68,1316.44 1179.29,1316.44 1179.29,1521.16
  pour cut-out: 4012.29,183.02 4012.29,171.92 4006.54,171.92 4006.54,183.02
  text ".layer_Name" at 11119.18,-642.91 h100
L3:
  pour cut-out: 3637.36,2799.98 3654.18,2799.98 3654.18,2794.38 3637.36,2794.38
  text ".layer_Name" at 11119.18,-642.91 h100
L4:
  region net U28_SW2: 1802.16,747.51 1802.16,607.34 1772.62,577.81 1772.62,490.08 1767.89,485.34 1735.73,485.34 1729.86,491.22 1729.86,588.36 1774.86,633.36 1774.86,761.11 1788.55,761.11
  region net U28_SW1: 1629.45,747.51 1629.45,607.34 1658.98,577.81 1658.98,491.6 1664.82,485.76 1694.91,485.76 1701.75,492.6 1701.75,588.36 1656.75,633.36 1656.75,761.11 1643.05,761.11
  region net VPD_output: 1365.95,855.31 1365.95,794.6 1374.81,785.74 1418.25,785.74 1426.87,794.36 1426.87,858.07 1417.13,867.81 1378.45,867.81
  text ".layer_Name" at 11119.18,-642.91 h100
L5:
  pour cut-out: 2254.04,211.87 2253.78,211.87 ccw(c2253.78,199.75) 2241.65,199.75 ccw(c2253.91,199.75) 2253.91,187.49 ccw(c2253.91,199.75) 2266.16,199.75 2266.16,199.92 ccw(c2254.17,199.92) 2254.17,211.91
  pour cut-out: 2254.04,243.37 2253.78,243.37 ccw(c2253.78,231.24) 2241.65,231.24 ccw(c2253.91,231.24) 2253.91,218.99 ccw(c2253.91,231.24) 2266.16,231.24 2266.16,231.42 ccw(c2254.17,231.42) 2254.17,243.41
  text ".layer_Name" at 11136.67,-642.91 h100
L2:
  text ".layer_Name" at 11116.67,-642.15 h100
L6:
  region net VSYS_3V3: 3111.95,868.36 3124.78,855.53 3177.07,855.53 3183.46,861.92 3183.46,880.72 3161.56,902.62 3111.95,902.62
  region net VSYS_3V3: 2906.61,1919.92 2856.53,1919.92 2846.05,1909.44 2846.05,1882.26 2858.21,1870.1 2906.61,1870.1
  region net VBUS_5V0_TYPEC_A: 3434.77,605.77 3434.77,595.55 3439.16,591.16 3472.39,591.16 3477.09,595.85 3477.09,608.68 3474.14,611.63 3440.64,611.63
  region net VDD_5V: 3491.28,788.85 3446.92,788.85 3432.25,774.18 3432.25,753.1 3446.3,739.04 3491.28,739.04
  text ".layer_Name" at 11123.85,-640.37 h100
L7:
  text ".layer_Name" at 11116.67,-642.15 h100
